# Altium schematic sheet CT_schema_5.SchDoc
size 283 x 147 mm
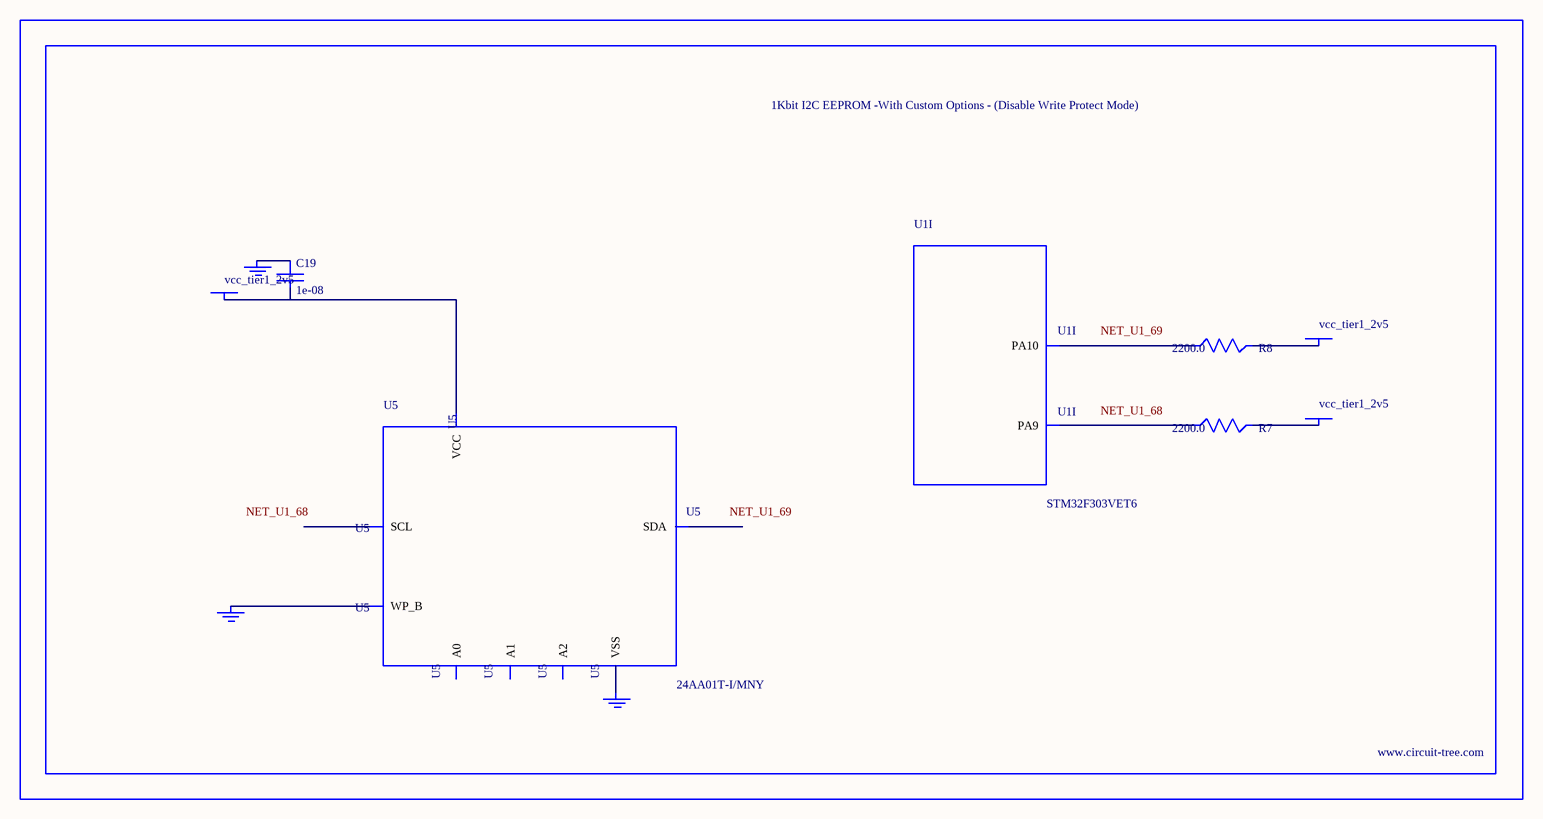
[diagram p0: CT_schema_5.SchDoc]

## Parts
BORDER4  (no value)
C19  1e-08  [C0402]
GND_INSTANCE_4_0  (no value)
GND_INSTANCE_4_1  (no value)
GND_INSTANCE_4_2  (no value)
POWER_INSTANCE_4_0  vcc_tier1_2v5
POWER_INSTANCE_4_1  vcc_tier1_2v5
POWER_INSTANCE_4_2  vcc_tier1_2v5
R7  2200.0  [R0603]
R8  2200.0  [R0603]
U1  STM32F303VET6  [LQFP100]  (part I of 9)
U5  24AA01T-I/MNY  [TDFN-8/6MM]

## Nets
NetC19_1: C19.1 GND_INSTANCE_4_1.0(GND)
NetC19_2: C19.2 POWER_INSTANCE_4_0.0(PWR) U5.8(VCC)
NetGND_INSTANCE_4_0_0: GND_INSTANCE_4_0.0(GND) U5.7(WP_B)
NetGND_INSTANCE_4_2_0: GND_INSTANCE_4_2.0(GND) U5.4(VSS)
NetPOWER_INSTANCE_4_1_0: POWER_INSTANCE_4_1.0(PWR) R7.2
NetPOWER_INSTANCE_4_2_0: POWER_INSTANCE_4_2.0(PWR) R8.2
NetR7_1: R7.1 U1.68(PA9)
NetR8_1: R8.1 U1.69(PA10)

Not connected (* = marked no-connect by the designer): U5 1(A0) 2(A1) 3(A2) 5(SDA) 6(SCL)

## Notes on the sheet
- Labels drawn without touching a wire or pin: NET_U1_68, NET_U1_69

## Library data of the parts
BORDER4 = BORDER_PAGE4
C19 = C0402C103K3RAC
GND_INSTANCE_4_0-GND_INSTANCE_4_2 = GND
POWER_INSTANCE_4_0-POWER_INSTANCE_4_2 = PWR
R7 R8 = RC0603JR-072K2L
